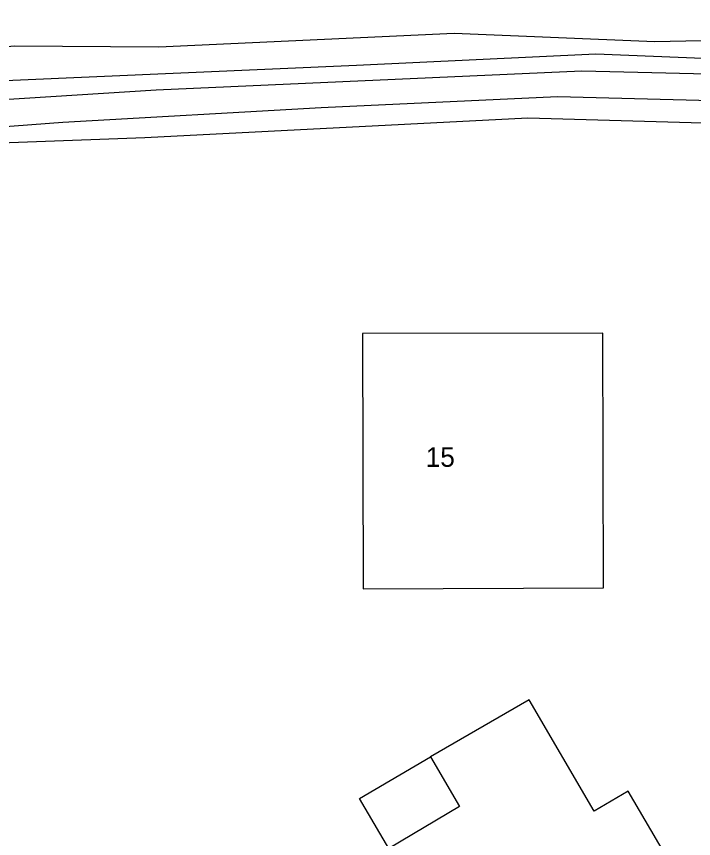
# Model space of a CAD drawing. Extents: x 128999 to 131010, y 395498 to 399007.
# Drawn here: x 130751 to 130785.71, y 395583.9 to 395626 of the extents above; entities that cross this region are included whole.
import ezdxf

# ---------------------------------------------------------------- set-up
doc = ezdxf.new("R2010")
doc.units = 0
for name, color, linetype in [('gg-afsc-erfafscheiding', 7, 'Continuous'), ('gg-anno-huisnummerreeks BGT', 7, 'Continuous'), ('gg-bbg-gedigitaliseerde bebouwing', 7, 'Continuous'), ('gg-bbg-hoofdgebouw', 7, 'Continuous'), ('gg-bbg-luifel en loopbrug', 7, 'Continuous'), ('gg-knt-onverhard', 7, 'Continuous'), ('gg-kntw-bovenkant insteek waterloop', 7, 'Continuous'), ('gg-kntw-waterlijn', 7, 'Continuous')]:
    doc.layers.add(name, color=color, linetype=linetype)

msp = doc.modelspace()

# ---------------------------------------------------------------- linework, layer by layer
at = {"layer": 'gg-afsc-erfafscheiding'}
msp.add_lwpolyline([(130730.321, 395617.924), (130745.546, 395619.352), (130757.583, 395619.802), (130777.206, 395620.804), (130789.766, 395620.447)], dxfattribs=at)
at = {"layer": 'gg-bbg-gedigitaliseerde bebouwing'}
for points in [[(130768.779, 395596.691), (130781.09, 395596.74), (130781.06, 395609.79), (130768.743, 395609.76)], [(130785.098, 395581.669), (130782.35, 395586.32), (130780.62, 395585.31), (130777.281, 395591.012), (130772.219, 395588.087)]]:
    msp.add_lwpolyline(points, dxfattribs=at)
at = {"layer": 'gg-bbg-hoofdgebouw'}
msp.add_line((130768.743, 395609.76), (130768.779, 395596.691), dxfattribs=at)
msp.add_lwpolyline([(130772.219, 395588.087), (130773.71, 395585.541), (130770.084, 395583.394)], dxfattribs=at)
at = {"layer": 'gg-bbg-luifel en loopbrug'}
msp.add_lwpolyline([(130770.084, 395583.394), (130768.582, 395585.949), (130772.219, 395588.087)], dxfattribs=at)
at = {"layer": 'gg-knt-onverhard'}
msp.add_lwpolyline([(130615.159, 395622.922), (130621.506, 395624.27), (130633.11, 395626.302), (130644.35, 395626.782), (130659.493, 395627.131), (130664.152, 395626.846), (130665.241, 395625.913), (130668.469, 395623.317), (130670.428, 395621.941), (130672.783, 395619.956), (130678.342, 395618.406), (130699.265, 395619.793), (130730.254, 395622.76), (130742.214, 395623.632), (130750.886, 395624.504), (130758.309, 395624.451), (130773.435, 395625.148), (130783.717, 395624.719), (130791.653, 395624.899), (130796.196, 395624.705)], dxfattribs=at)
at = {"layer": 'gg-kntw-bovenkant insteek waterloop'}
msp.add_lwpolyline([(130796.324, 395623.432), (130780.696, 395624.08), (130768.44, 395623.495), (130750.813, 395622.726), (130730.008, 395621.178)], dxfattribs=at)
at = {"layer": 'gg-kntw-waterlijn'}
for points in [[(130730.075, 395620.476), (130758.16, 395622.238), (130779.981, 395623.222), (130789.29, 395623.002), (130796.4, 395622.678), (130798.83, 395622.552)], [(130730.232, 395618.85), (130753.374, 395620.593), (130766.613, 395621.338), (130778.728, 395621.902), (130796.524, 395621.449), (130798.954, 395621.318)]]:
    msp.add_lwpolyline(points, dxfattribs=at)

# ---------------------------------------------------------------- texts
at = {"layer": 'gg-anno-huisnummerreeks BGT'}
msp.add_text('15', height=1, rotation=0.2, dxfattribs=at).set_placement((130771.984, 395602.934))

doc.saveas('drawing.dxf')
